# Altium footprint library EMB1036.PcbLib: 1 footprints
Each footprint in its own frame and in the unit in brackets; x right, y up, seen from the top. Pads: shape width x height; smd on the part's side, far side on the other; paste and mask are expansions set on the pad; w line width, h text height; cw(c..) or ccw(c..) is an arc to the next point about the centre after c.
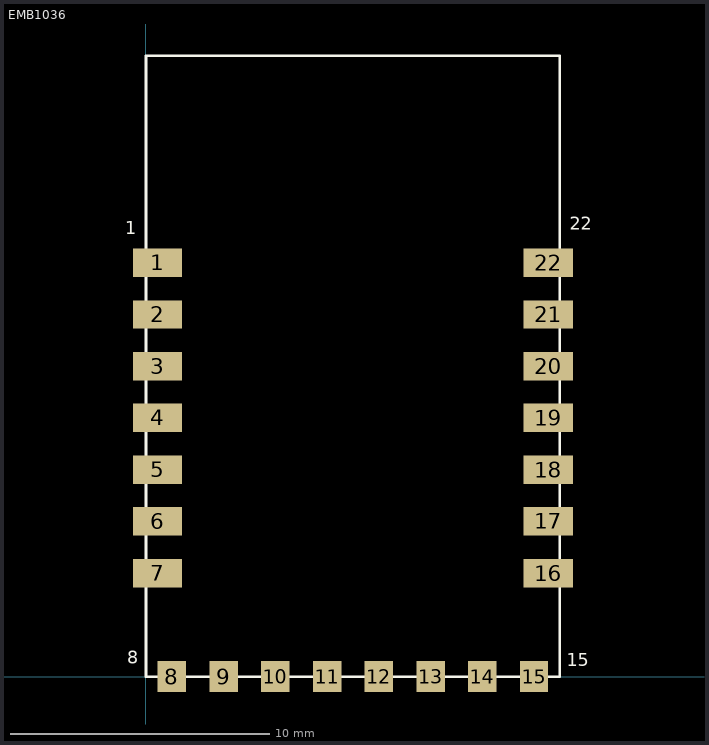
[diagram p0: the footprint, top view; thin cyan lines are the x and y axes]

## EMB1036 [mm]
height 0.9
pads (22):
  rect 1.9x1.1 smd: 1(0.457,16.002) 2(0.457,14.002) 3(0.457,12.002) 4(0.457,10.002) 5(0.457,8.002) 6(0.457,6.002) 7(0.457,4.002) 16(15.557,4.002) 17(15.557,6.002) 18(15.557,8.002) 19(15.557,10.002) 20(15.557,12.002) 21(15.557,14.002) 22(15.557,16.002)
  rect 1.1x1.2 smd: 8(1.007,0) 9(3.007,0) 10(5.007,0) 11(7.007,0) 12(9.007,0) 13(11.007,0) 14(13.007,0) 15(15.007,0)
Top Overlay:
  lines w0.1: 0.007,24.002 0.007,0.002 16.007,0.002 16.007,24.002
  lines w0.102: 0.007,24.002 16.007,24.002
  text "22" at 16.383,17.272 h0.5
  text "15" at 16.281,0.406 h0.5
  text "8" at -0.711,0.508 h0.5
  text "1" at -0.787,17.094 h0.5
3D body: height 1.8, standoff 1.2, extent 7.94,6.949 12.99,11.999
3D body "User Library-3225-1.STEP": height 1.81, standoff 1.2, extent 1.981,9.55 5.181,12.05
3D body "SW3dPS-U.FL-R-SMT-1.STEP": height 2.45, standoff 1.19, extent 2.908,13.462 5.908,16.562
3D body: height 1.2, standoff 0.01, extent 0.462,16.596 15.473,23.683
3D body: height 1.2, standoff 0, extent 0.01,-0.031 16.003,23.99
3D body "User Library-sop-8.STEP": height 1.6, standoff 0, extent 1.122,3.024 6.142,9.066
3D body: height 1.2, standoff 0.02, extent 0.506,-0.095 1.507,0.409
3D body: height 1.2, standoff 0, extent 0.71,0.9 1.31,1.5
3D body: height 1.2, standoff 0, extent 0.41,0.589 1.61,1.789
3D body: height 1.2, standoff 0.01, extent 0.51,0.116 1.51,1.2
3D body: height 1.2, standoff 0.02, extent 14.506,-0.105 15.507,0.399
3D body: height 1.2, standoff 0, extent 14.71,0.89 15.31,1.49
3D body: height 1.2, standoff 0, extent 14.41,0.579 15.61,1.779
3D body: height 1.2, standoff 0.01, extent 14.51,0.106 15.51,1.19
3D body: height 1.2, standoff 0.02, extent 12.506,-0.105 13.507,0.399
3D body: height 1.2, standoff 0, extent 12.71,0.89 13.31,1.49
3D body: height 1.2, standoff 0, extent 12.41,0.579 13.61,1.779
3D body: height 1.2, standoff 0.01, extent 12.51,0.106 13.51,1.19
3D body: height 1.2, standoff 0.02, extent 10.516,-0.115 11.517,0.389
3D body: height 1.2, standoff 0, extent 10.72,0.88 11.32,1.48
3D body: height 1.2, standoff 0, extent 10.42,0.569 11.62,1.769
3D body: height 1.2, standoff 0.01, extent 10.52,0.096 11.52,1.18
3D body: height 1.2, standoff 0.02, extent 8.506,-0.105 9.507,0.399
3D body: height 1.2, standoff 0, extent 8.71,0.89 9.31,1.49
3D body: height 1.2, standoff 0, extent 8.41,0.579 9.61,1.779
3D body: height 1.2, standoff 0.01, extent 8.51,0.106 9.51,1.19
3D body: height 1.2, standoff 0.02, extent 6.506,-0.095 7.507,0.409
3D body: height 1.2, standoff 0, extent 6.71,0.9 7.31,1.5
3D body: height 1.2, standoff 0, extent 6.41,0.589 7.61,1.789
3D body: height 1.2, standoff 0.01, extent 6.51,0.116 7.51,1.2
3D body: height 1.2, standoff 0.02, extent 4.506,-0.095 5.507,0.409
3D body: height 1.2, standoff 0, extent 4.71,0.9 5.31,1.5
3D body: height 1.2, standoff 0, extent 4.41,0.589 5.61,1.789
3D body: height 1.2, standoff 0.01, extent 4.51,0.116 5.51,1.2
3D body: height 1.2, standoff 0.01, extent 2.519,0.096 3.52,1.18
3D body: height 1.2, standoff 0, extent 2.42,0.569 3.619,1.769
3D body: height 1.2, standoff 0, extent 2.72,0.88 3.319,1.48
3D body: height 1.2, standoff 0.02, extent 2.516,-0.115 3.517,0.389
3D body: height 1.2, standoff 0.01, extent 15.533,3.418 16.024,4.418
3D body: height 1.2, standoff 0.01, extent 15.533,5.424 16.024,6.425
3D body: height 1.2, standoff 0.01, extent 15.533,7.431 16.024,8.431
3D body: height 1.2, standoff 0.01, extent 15.533,9.437 16.024,10.438
3D body: height 1.2, standoff 0.01, extent 15.533,11.419 16.024,12.419
3D body: height 1.2, standoff 0.01, extent 15.533,13.425 16.024,14.426
3D body: height 1.2, standoff 0.01, extent 15.533,15.432 16.024,16.432
3D body: height 1.2, standoff 0.01, extent 0.009,3.443 0.5,4.444
3D body: height 1.2, standoff 0.01, extent 0.009,5.424 0.5,6.425
3D body: height 1.2, standoff 0.01, extent 0.009,7.431 0.5,8.431
3D body: height 1.2, standoff 0.01, extent 0.009,9.437 0.5,10.438
3D body: height 1.2, standoff 0.01, extent 0.009,11.419 0.5,12.419
3D body: height 1.2, standoff 0.01, extent -0.017,13.425 0.474,14.426
3D body: height 1.2, standoff 0.01, extent -0.017,15.432 0.474,16.432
